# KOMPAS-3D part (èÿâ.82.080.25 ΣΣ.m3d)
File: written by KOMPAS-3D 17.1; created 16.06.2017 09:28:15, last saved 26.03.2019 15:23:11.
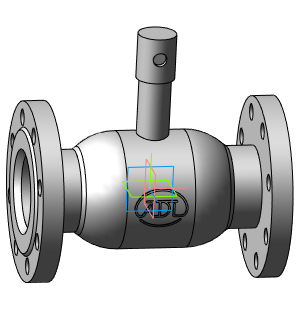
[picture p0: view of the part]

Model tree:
1. Операция без истории:2  (labels: Сталь 20  ГОСТ 1050-88)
